(* Logix 5000 project; controller PDPMV1_60_v15 vendor 1 type 14 code 65 rev 15.1; software revision 15.00; part 3 of 3 *)
(* tags used below, declared in another part *)
   MVI69PDPMV1 : PDPMV1_ModuleDef;
(* MainProgram, continued *)

ROUTINE ReadStatus   (* ladder *)
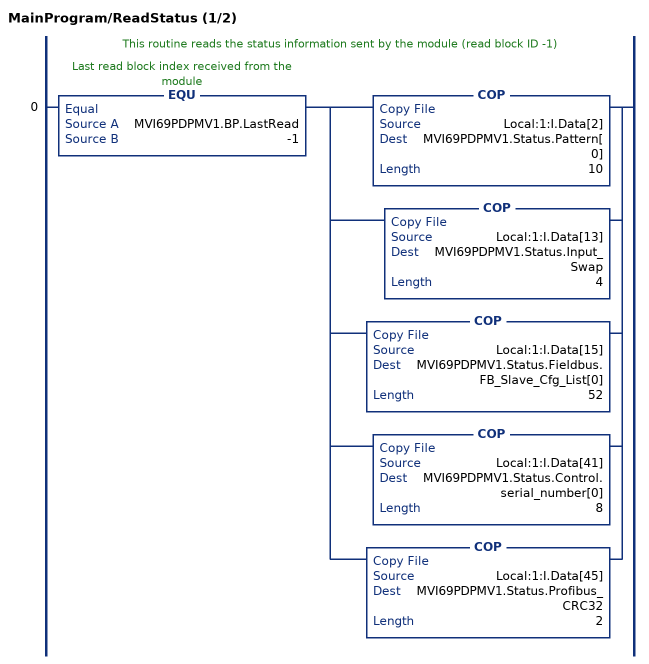
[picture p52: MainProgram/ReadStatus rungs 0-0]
   // This routine reads the status information sent by the module (read block ID -1)
   0: EQU(MVI69PDPMV1.BP.LastRead,-1)[COP(Local:1:I.Data[2],MVI69PDPMV1.Status.Pattern[0],10) ,COP(Local:1:I.Data[13],MVI69PDPMV1.Status.Input_Swap,4) ,COP(Local:1:I.Data[15],MVI69PDPMV1.Status.Fieldbus.FB_Slave_Cfg_List[0],52) ,COP(Local:1:I.Data[41],MVI69PDPMV1.Status.Control.serial_number[0],8) ,COP(Local:1:I.Data[45],MVI69PDPMV1.Status.Profibus_CRC32,2) ];
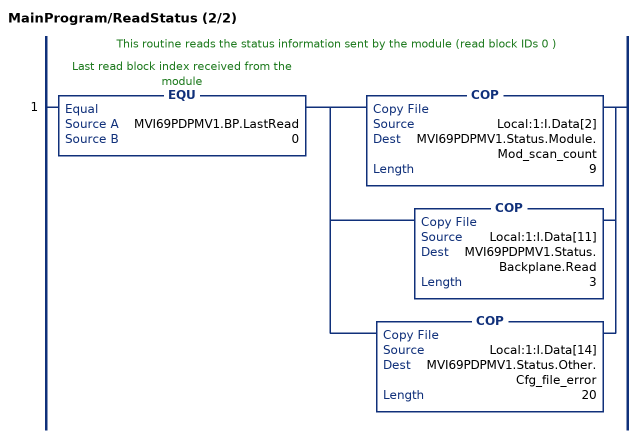
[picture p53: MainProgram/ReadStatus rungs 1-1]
   // This routine reads the status information sent by the module (read block IDs 0 )
   1: EQU(MVI69PDPMV1.BP.LastRead,0)[COP(Local:1:I.Data[2],MVI69PDPMV1.Status.Module.Mod_scan_count,9) ,COP(Local:1:I.Data[11],MVI69PDPMV1.Status.Backplane.Read,3) ,COP(Local:1:I.Data[14],MVI69PDPMV1.Status.Other.Cfg_file_error,20) ];
END_ROUTINE

ROUTINE WriteData   (* ladder *)
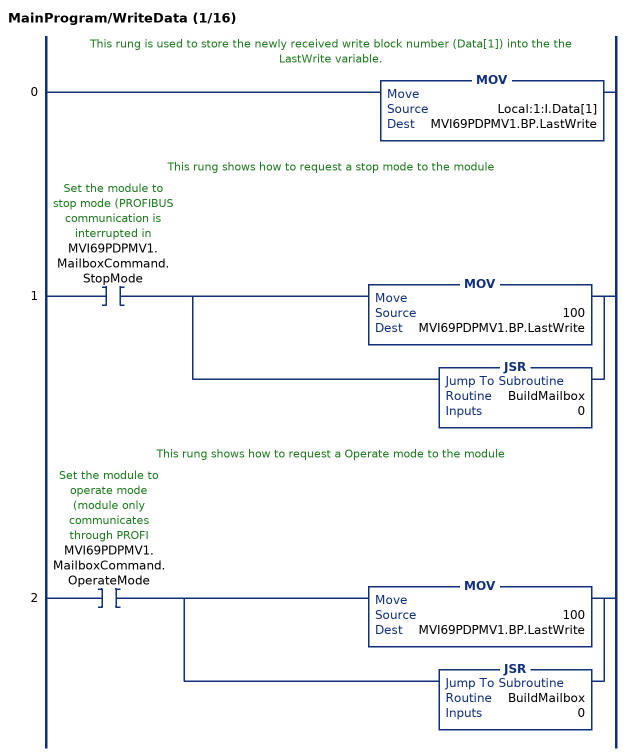
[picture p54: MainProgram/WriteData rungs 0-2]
   // This rung is used to store the newly received write block number (Data[1]) into the the LastWrite variable.
   0: MOV(Local:1:I.Data[1],MVI69PDPMV1.BP.LastWrite);
   // This rung shows how to request a stop mode to the module
   1: XIC(MVI69PDPMV1.MailboxCommand.StopMode)[MOV(100,MVI69PDPMV1.BP.LastWrite) ,JSR(BuildMailbox,0) ];
   // This rung shows how to request a Operate mode to the module
   2: XIC(MVI69PDPMV1.MailboxCommand.OperateMode)[MOV(100,MVI69PDPMV1.BP.LastWrite) ,JSR(BuildMailbox,0) ];
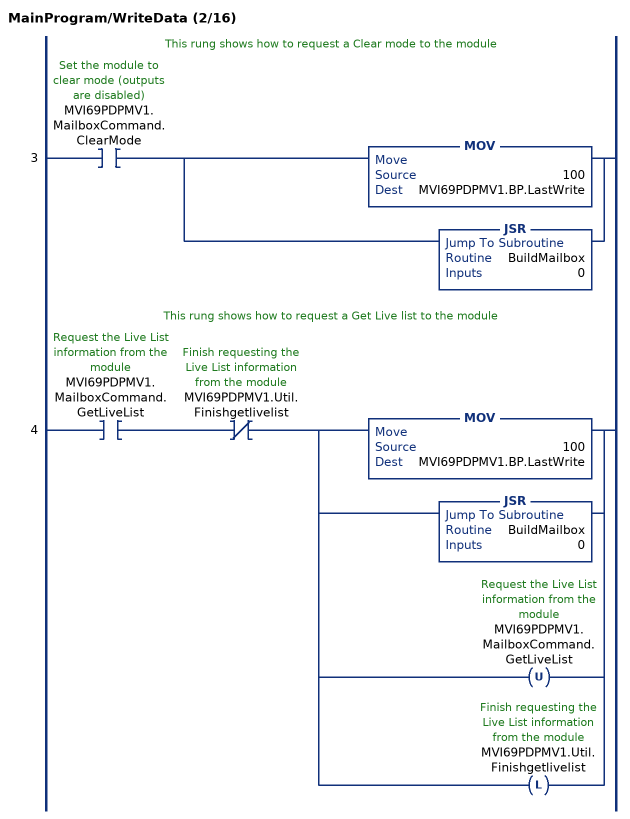
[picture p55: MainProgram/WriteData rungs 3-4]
   // This rung shows how to request a Clear mode to the module
   3: XIC(MVI69PDPMV1.MailboxCommand.ClearMode)[MOV(100,MVI69PDPMV1.BP.LastWrite) ,JSR(BuildMailbox,0) ];
   // This rung shows how to request a Get Live list to the module
   4: XIC(MVI69PDPMV1.MailboxCommand.GetLiveList)XIO(MVI69PDPMV1.Util.Finishgetlivelist)[MOV(100,MVI69PDPMV1.BP.LastWrite) ,JSR(BuildMailbox,0) ,OTU(MVI69PDPMV1.MailboxCommand.GetLiveList) ,OTL(MVI69PDPMV1.Util.Finishgetlivelist) ];
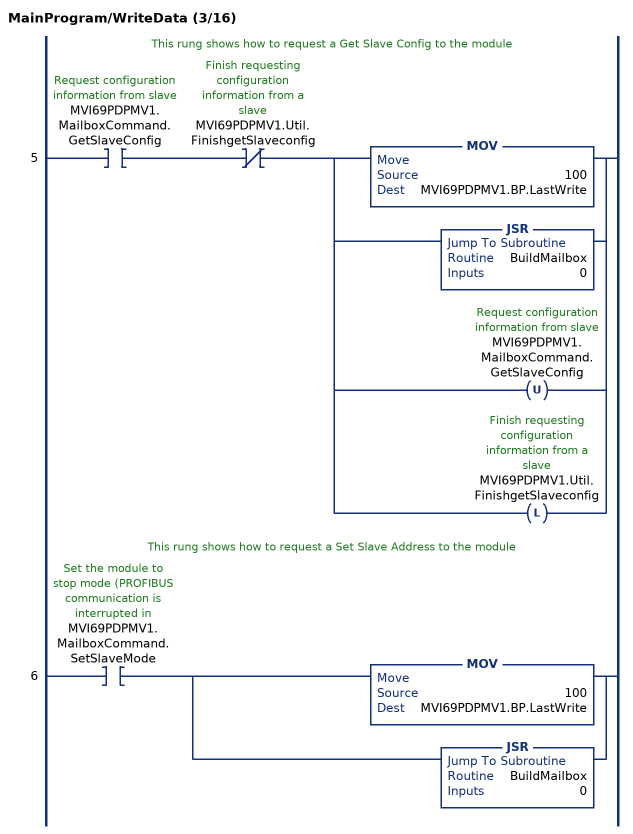
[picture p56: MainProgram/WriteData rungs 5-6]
   // This rung shows how to request a Get Slave Config to the module
   5: XIC(MVI69PDPMV1.MailboxCommand.GetSlaveConfig)XIO(MVI69PDPMV1.Util.FinishgetSlaveconfig)[MOV(100,MVI69PDPMV1.BP.LastWrite) ,JSR(BuildMailbox,0) ,OTU(MVI69PDPMV1.MailboxCommand.GetSlaveConfig) ,OTL(MVI69PDPMV1.Util.FinishgetSlaveconfig) ];
   // This rung shows how to request a Set Slave Address to the module
   6: XIC(MVI69PDPMV1.MailboxCommand.SetSlaveMode)[MOV(100,MVI69PDPMV1.BP.LastWrite) ,JSR(BuildMailbox,0) ];
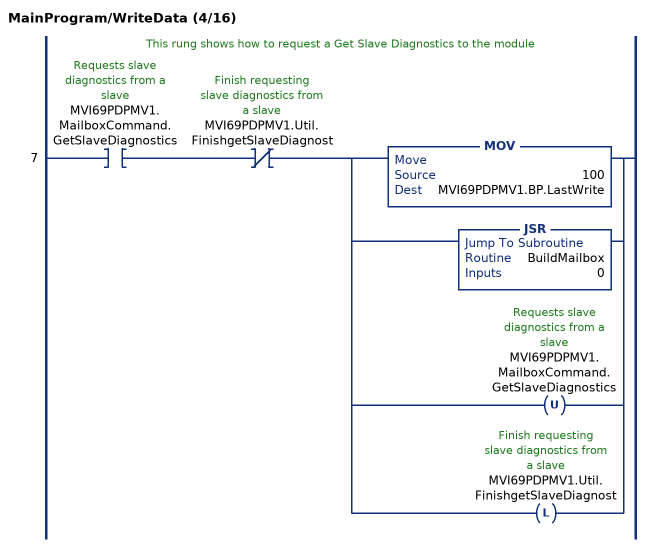
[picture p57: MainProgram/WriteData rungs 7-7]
   // This rung shows how to request a Get Slave Diagnostics to the module
   7: XIC(MVI69PDPMV1.MailboxCommand.GetSlaveDiagnostics)XIO(MVI69PDPMV1.Util.FinishgetSlaveDiagnost)[MOV(100,MVI69PDPMV1.BP.LastWrite) ,JSR(BuildMailbox,0) ,OTU(MVI69PDPMV1.MailboxCommand.GetSlaveDiagnostics) ,OTL(MVI69PDPMV1.Util.FinishgetSlaveDiagnost) ];
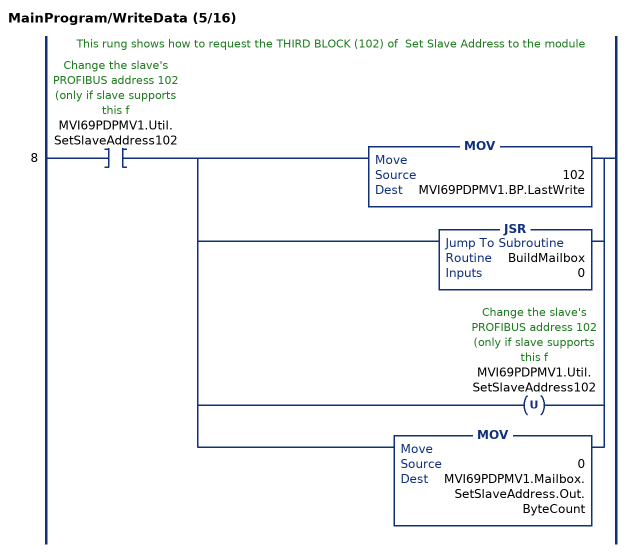
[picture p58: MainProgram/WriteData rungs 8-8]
   // This rung shows how to request the THIRD BLOCK (102) of  Set Slave Address to the module
   8: XIC(MVI69PDPMV1.Util.SetSlaveAddress102)[MOV(102,MVI69PDPMV1.BP.LastWrite) ,JSR(BuildMailbox,0) ,OTU(MVI69PDPMV1.Util.SetSlaveAddress102) ,MOV(0,MVI69PDPMV1.Mailbox.SetSlaveAddress.Out.ByteCount) ];
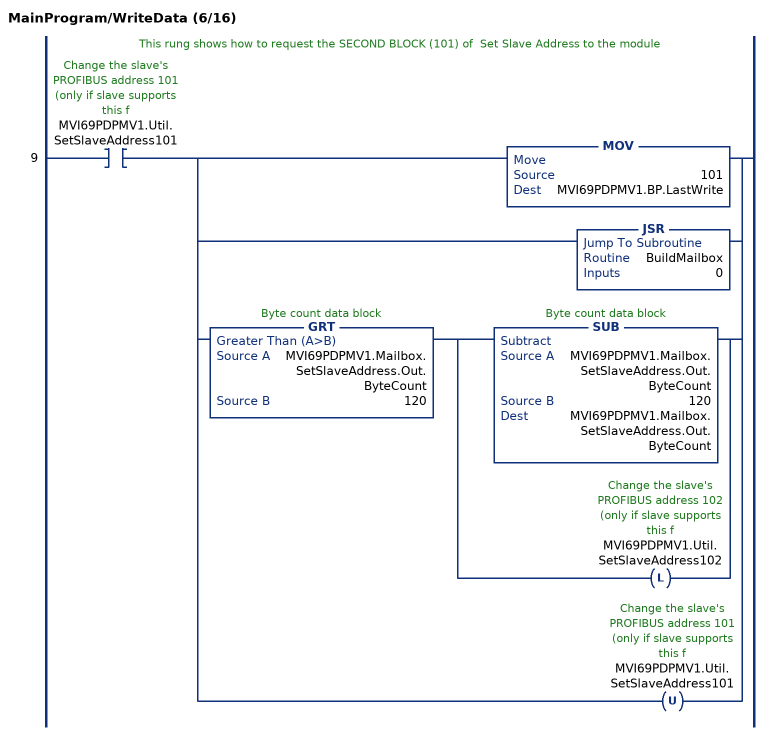
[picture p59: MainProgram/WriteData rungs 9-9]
   // This rung shows how to request the SECOND BLOCK (101) of  Set Slave Address to the module
   9: XIC(MVI69PDPMV1.Util.SetSlaveAddress101)[MOV(101,MVI69PDPMV1.BP.LastWrite) ,JSR(BuildMailbox,0) ,GRT(MVI69PDPMV1.Mailbox.SetSlaveAddress.Out.ByteCount,120) [SUB(MVI69PDPMV1.Mailbox.SetSlaveAddress.Out.ByteCount,120,MVI69PDPMV1.Mailbox.SetSlaveAddress.Out.ByteCount) ,OTL(MVI69PDPMV1.Util.SetSlaveAddress102) ] ,OTU(MVI69PDPMV1.Util.SetSlaveAddress101) ];
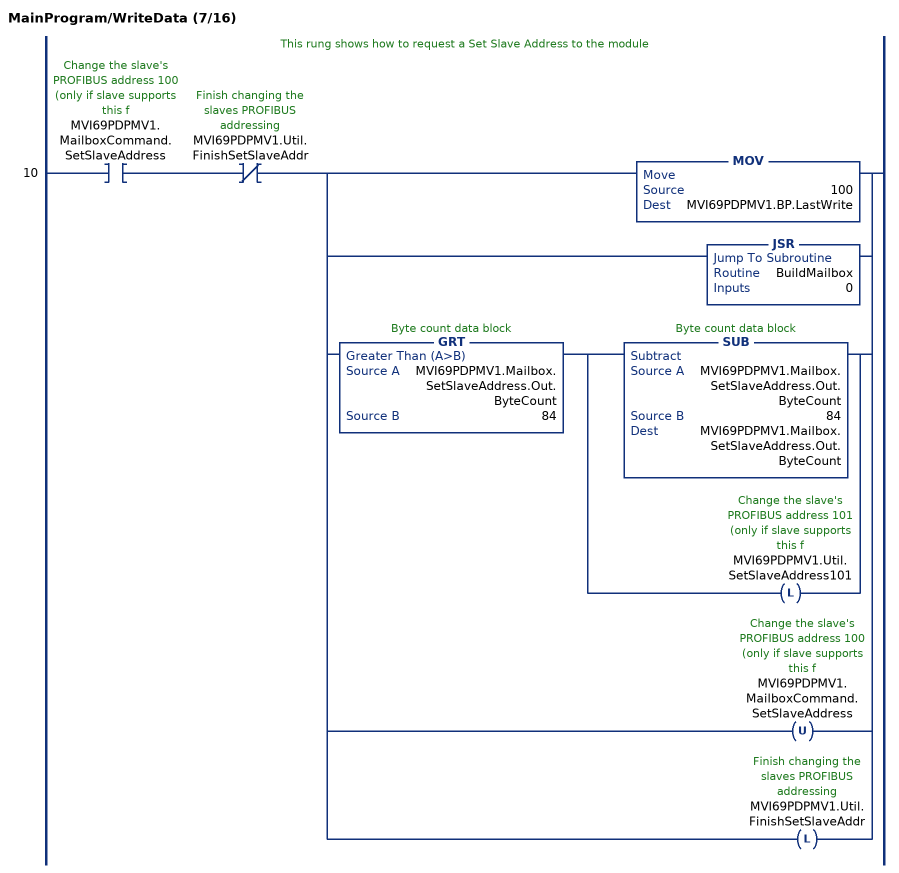
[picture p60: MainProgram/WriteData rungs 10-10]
   // This rung shows how to request a Set Slave Address to the module
   10: XIC(MVI69PDPMV1.MailboxCommand.SetSlaveAddress)XIO(MVI69PDPMV1.Util.FinishSetSlaveAddr)[MOV(100,MVI69PDPMV1.BP.LastWrite) ,JSR(BuildMailbox,0) ,GRT(MVI69PDPMV1.Mailbox.SetSlaveAddress.Out.ByteCount,84) [SUB(MVI69PDPMV1.Mailbox.SetSlaveAddress.Out.ByteCount,84,MVI69PDPMV1.Mailbox.SetSlaveAddress.Out.ByteCount) ,OTL(MVI69PDPMV1.Util.SetSlaveAddress101) ] ,OTU(MVI69PDPMV1.MailboxCommand.SetSlaveAddress) ,OTL(MVI69PDPMV1.Util.FinishSetSlaveAddr) ];
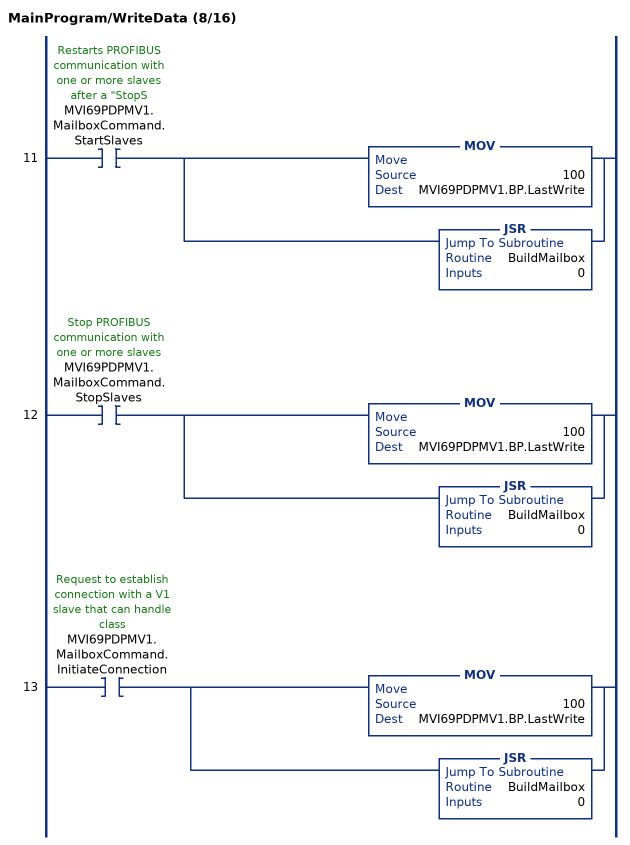
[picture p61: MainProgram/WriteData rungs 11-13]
   11: XIC(MVI69PDPMV1.MailboxCommand.StartSlaves)[MOV(100,MVI69PDPMV1.BP.LastWrite) ,JSR(BuildMailbox,0) ];
   12: XIC(MVI69PDPMV1.MailboxCommand.StopSlaves)[MOV(100,MVI69PDPMV1.BP.LastWrite) ,JSR(BuildMailbox,0) ];
   13: XIC(MVI69PDPMV1.MailboxCommand.InitiateConnection)[MOV(100,MVI69PDPMV1.BP.LastWrite) ,JSR(BuildMailbox,0) ];
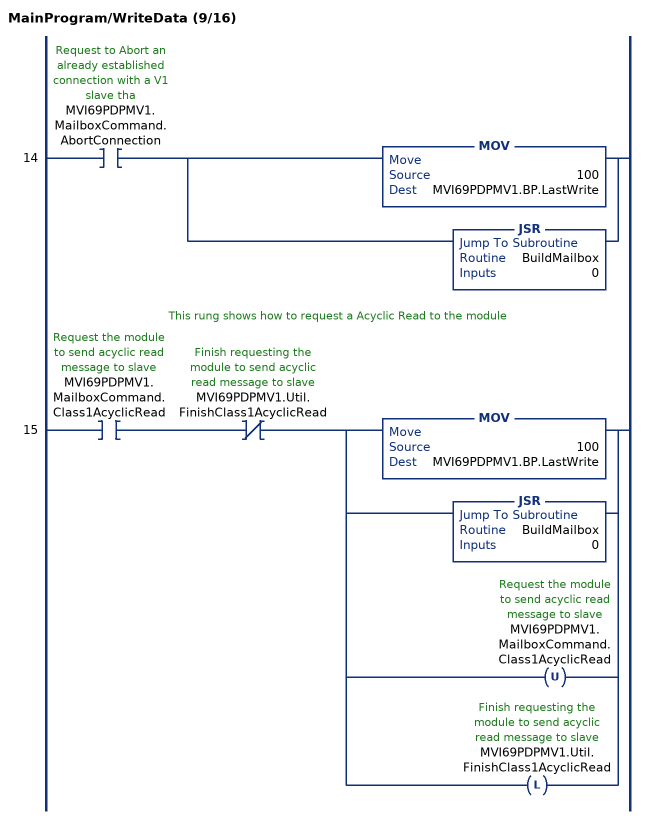
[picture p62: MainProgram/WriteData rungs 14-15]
   14: XIC(MVI69PDPMV1.MailboxCommand.AbortConnection)[MOV(100,MVI69PDPMV1.BP.LastWrite) ,JSR(BuildMailbox,0) ];
   // This rung shows how to request a Acyclic Read to the module
   15: XIC(MVI69PDPMV1.MailboxCommand.Class1AcyclicRead)XIO(MVI69PDPMV1.Util.FinishClass1AcyclicRead)[MOV(100,MVI69PDPMV1.BP.LastWrite) ,JSR(BuildMailbox,0) ,OTU(MVI69PDPMV1.MailboxCommand.Class1AcyclicRead) ,OTL(MVI69PDPMV1.Util.FinishClass1AcyclicRead) ];
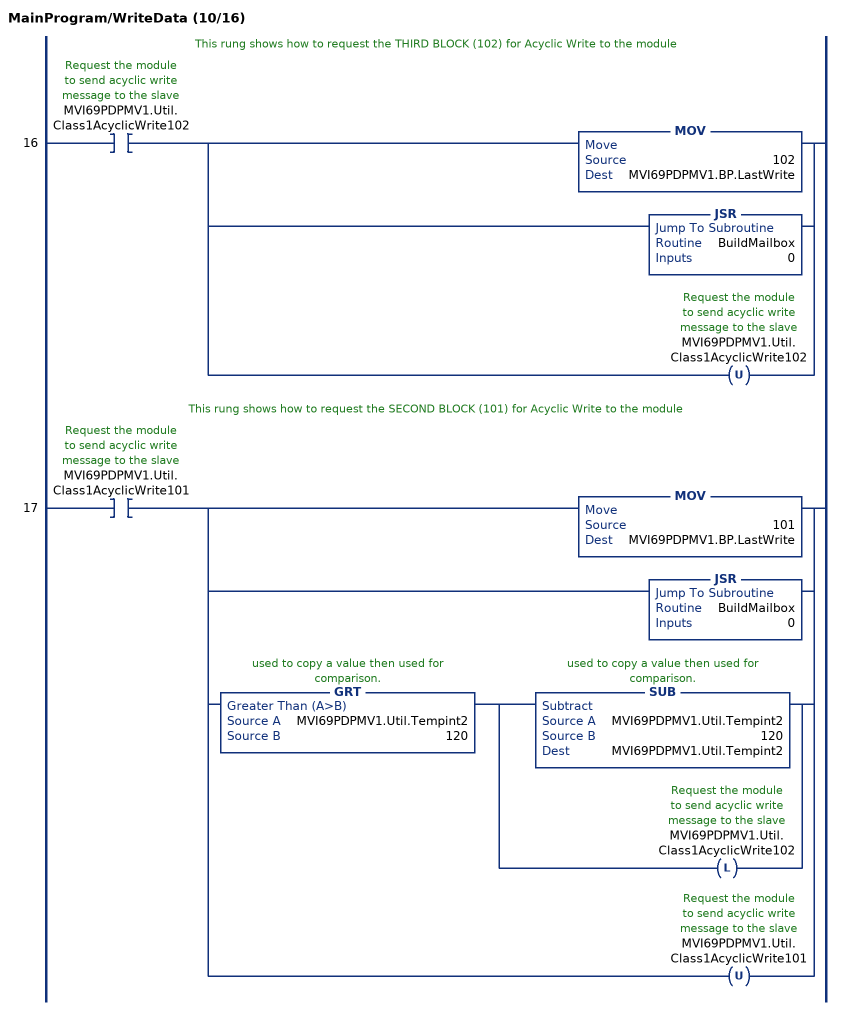
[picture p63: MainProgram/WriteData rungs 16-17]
   // This rung shows how to request the THIRD BLOCK (102) for Acyclic Write to the module
   16: XIC(MVI69PDPMV1.Util.Class1AcyclicWrite102)[MOV(102,MVI69PDPMV1.BP.LastWrite) ,JSR(BuildMailbox,0) ,OTU(MVI69PDPMV1.Util.Class1AcyclicWrite102) ];
   // This rung shows how to request the SECOND BLOCK (101) for Acyclic Write to the module
   17: XIC(MVI69PDPMV1.Util.Class1AcyclicWrite101)[MOV(101,MVI69PDPMV1.BP.LastWrite) ,JSR(BuildMailbox,0) ,GRT(MVI69PDPMV1.Util.Tempint2,120) [SUB(MVI69PDPMV1.Util.Tempint2,120,MVI69PDPMV1.Util.Tempint2) ,OTL(MVI69PDPMV1.Util.Class1AcyclicWrite102) ] ,OTU(MVI69PDPMV1.Util.Class1AcyclicWrite101) ];
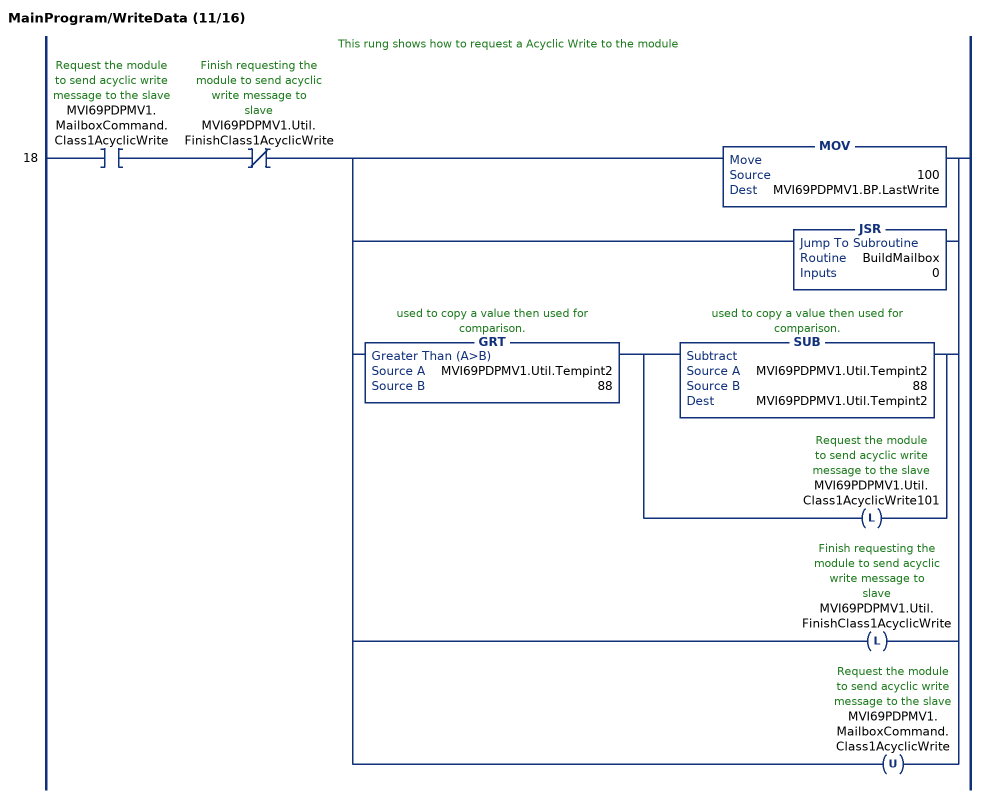
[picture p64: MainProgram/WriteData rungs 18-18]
   // This rung shows how to request a Acyclic Write to the module
   18: XIC(MVI69PDPMV1.MailboxCommand.Class1AcyclicWrite)XIO(MVI69PDPMV1.Util.FinishClass1AcyclicWrite)[MOV(100,MVI69PDPMV1.BP.LastWrite) ,JSR(BuildMailbox,0) ,GRT(MVI69PDPMV1.Util.Tempint2,88) [SUB(MVI69PDPMV1.Util.Tempint2,88,MVI69PDPMV1.Util.Tempint2) ,OTL(MVI69PDPMV1.Util.Class1AcyclicWrite101) ] ,OTL(MVI69PDPMV1.Util.FinishClass1AcyclicWrite) ,OTU(MVI69PDPMV1.MailboxCommand.Class1AcyclicWrite) ];
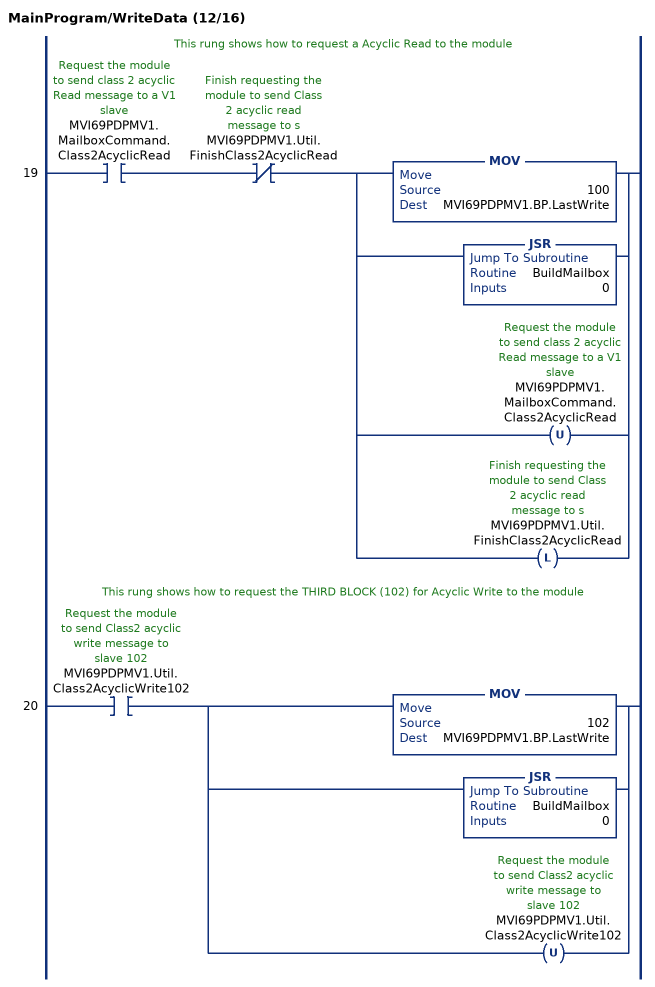
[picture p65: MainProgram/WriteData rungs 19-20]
   // This rung shows how to request a Acyclic Read to the module
   19: XIC(MVI69PDPMV1.MailboxCommand.Class2AcyclicRead)XIO(MVI69PDPMV1.Util.FinishClass2AcyclicRead)[MOV(100,MVI69PDPMV1.BP.LastWrite) ,JSR(BuildMailbox,0) ,OTU(MVI69PDPMV1.MailboxCommand.Class2AcyclicRead) ,OTL(MVI69PDPMV1.Util.FinishClass2AcyclicRead) ];
   // This rung shows how to request the THIRD BLOCK (102) for Acyclic Write to the module
   20: XIC(MVI69PDPMV1.Util.Class2AcyclicWrite102)[MOV(102,MVI69PDPMV1.BP.LastWrite) ,JSR(BuildMailbox,0) ,OTU(MVI69PDPMV1.Util.Class2AcyclicWrite102) ];
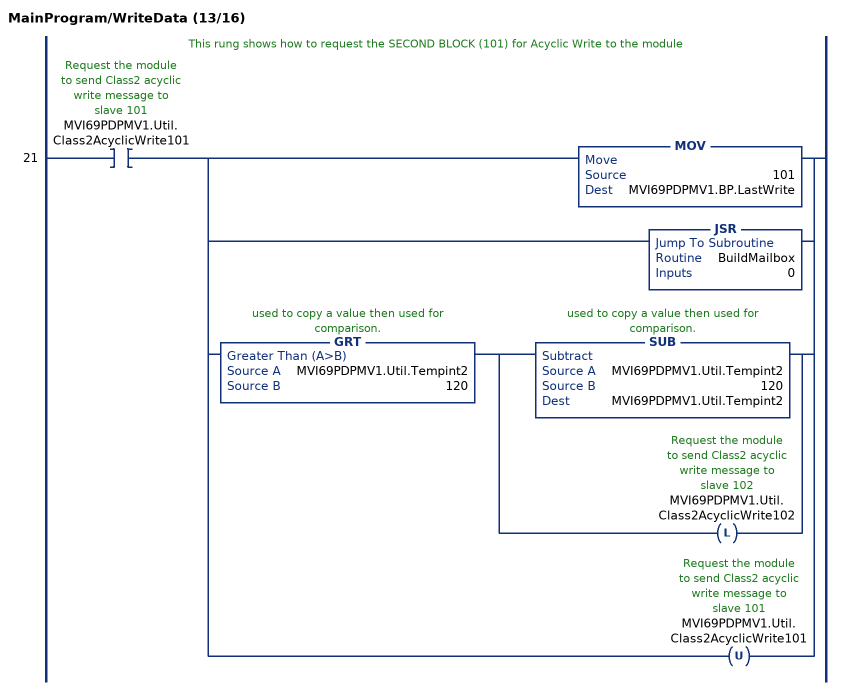
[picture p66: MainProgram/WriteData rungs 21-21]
   // This rung shows how to request the SECOND BLOCK (101) for Acyclic Write to the module
   21: XIC(MVI69PDPMV1.Util.Class2AcyclicWrite101)[MOV(101,MVI69PDPMV1.BP.LastWrite) ,JSR(BuildMailbox,0) ,GRT(MVI69PDPMV1.Util.Tempint2,120) [SUB(MVI69PDPMV1.Util.Tempint2,120,MVI69PDPMV1.Util.Tempint2) ,OTL(MVI69PDPMV1.Util.Class2AcyclicWrite102) ] ,OTU(MVI69PDPMV1.Util.Class2AcyclicWrite101) ];
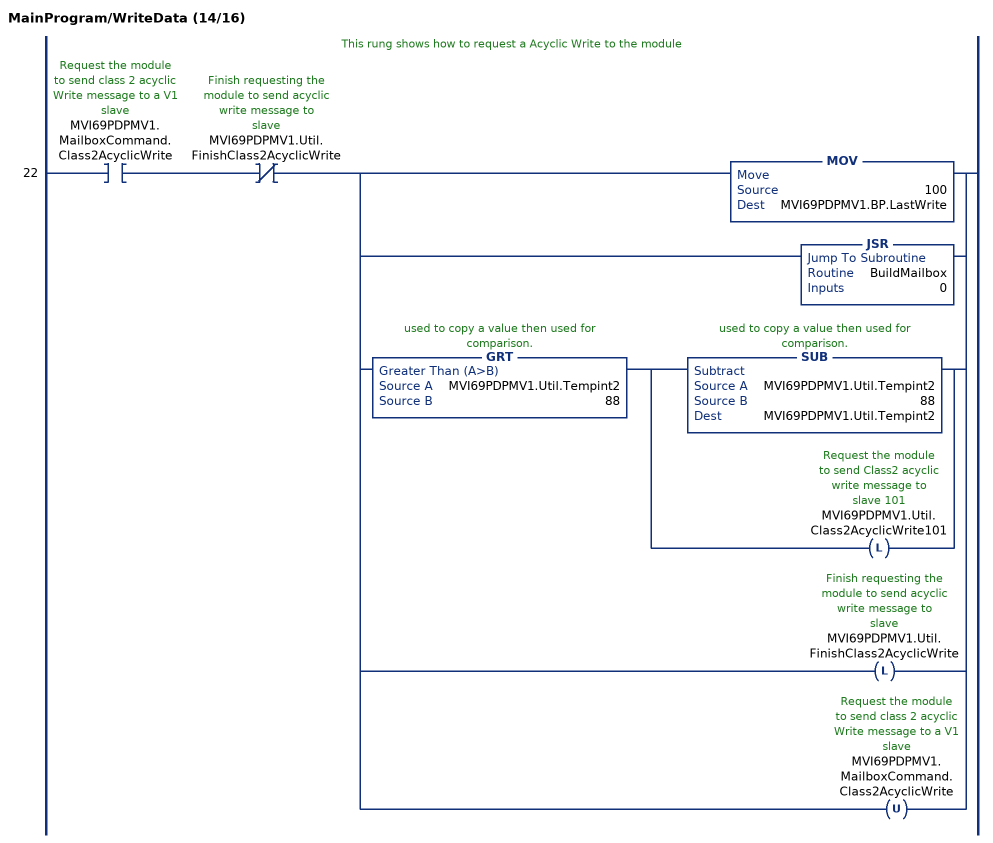
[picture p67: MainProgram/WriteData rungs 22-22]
   // This rung shows how to request a Acyclic Write to the module
   22: XIC(MVI69PDPMV1.MailboxCommand.Class2AcyclicWrite)XIO(MVI69PDPMV1.Util.FinishClass2AcyclicWrite)[MOV(100,MVI69PDPMV1.BP.LastWrite) ,JSR(BuildMailbox,0) ,GRT(MVI69PDPMV1.Util.Tempint2,88) [SUB(MVI69PDPMV1.Util.Tempint2,88,MVI69PDPMV1.Util.Tempint2) ,OTL(MVI69PDPMV1.Util.Class2AcyclicWrite101) ] ,OTL(MVI69PDPMV1.Util.FinishClass2AcyclicWrite) ,OTU(MVI69PDPMV1.MailboxCommand.Class2AcyclicWrite) ];
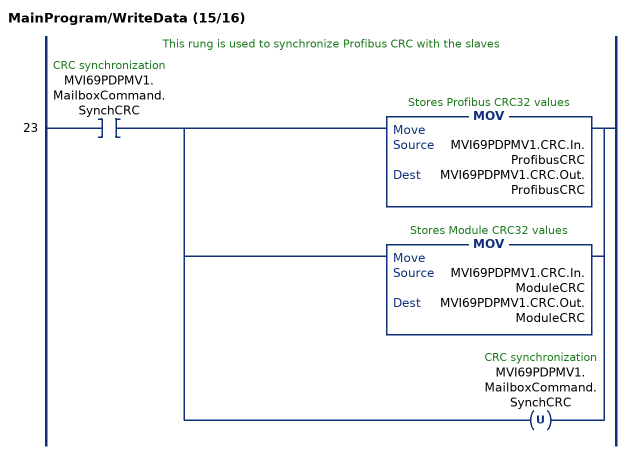
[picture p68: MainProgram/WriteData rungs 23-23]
   // This rung is used to synchronize Profibus CRC with the slaves
   23: XIC(MVI69PDPMV1.MailboxCommand.SynchCRC)[MOV(MVI69PDPMV1.CRC.In.ProfibusCRC,MVI69PDPMV1.CRC.Out.ProfibusCRC) ,MOV(MVI69PDPMV1.CRC.In.ModuleCRC,MVI69PDPMV1.CRC.Out.ModuleCRC) ,OTU(MVI69PDPMV1.MailboxCommand.SynchCRC) ];
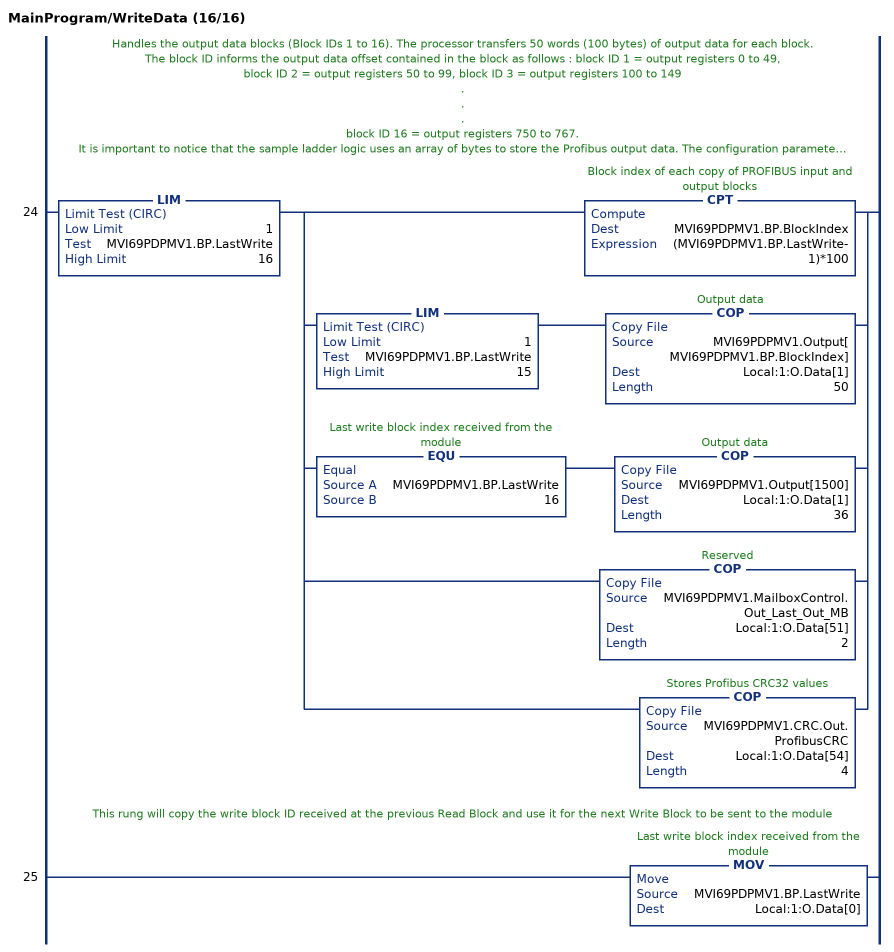
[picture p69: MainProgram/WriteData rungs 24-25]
   // Handles the output data blocks (Block IDs 1 to 16). The processor transfers 50 words (100 bytes) of output data for each block.
   // The block ID informs the output data offset contained in the block as follows : block ID 1 = output registers 0 to 49,
   // block ID 2 = output registers 50 to 99, block ID 3 = output registers 100 to 149
   // .
   // .
   // .
   // block ID 16 = output registers 750 to 767.
   // It is important to notice that the sample ladder logic uses an array of bytes to store the Profibus output data. The configuration parameter allows the user to configure the number of words (2 bytes each) to be transferred between the module and the processor.
   24: LIM(1,MVI69PDPMV1.BP.LastWrite,16)[CPT(MVI69PDPMV1.BP.BlockIndex,(MVI69PDPMV1.BP.LastWrite-1)*100) ,LIM(1,MVI69PDPMV1.BP.LastWrite,15) COP(MVI69PDPMV1.Output[MVI69PDPMV1.BP.BlockIndex],Local:1:O.Data[1],50) ,EQU(MVI69PDPMV1.BP.LastWrite,16) COP(MVI69PDPMV1.Output[1500],Local:1:O.Data[1],36) ,COP(MVI69PDPMV1.MailboxControl.Out_Last_Out_MB,Local:1:O.Data[51],2) ,COP(MVI69PDPMV1.CRC.Out.ProfibusCRC,Local:1:O.Data[54],4) ];
   // This rung will copy the write block ID received at the previous Read Block and use it for the next Write Block to be sent to the module
   25: MOV(MVI69PDPMV1.BP.LastWrite,Local:1:O.Data[0]);
END_ROUTINE
END_PROGRAM
